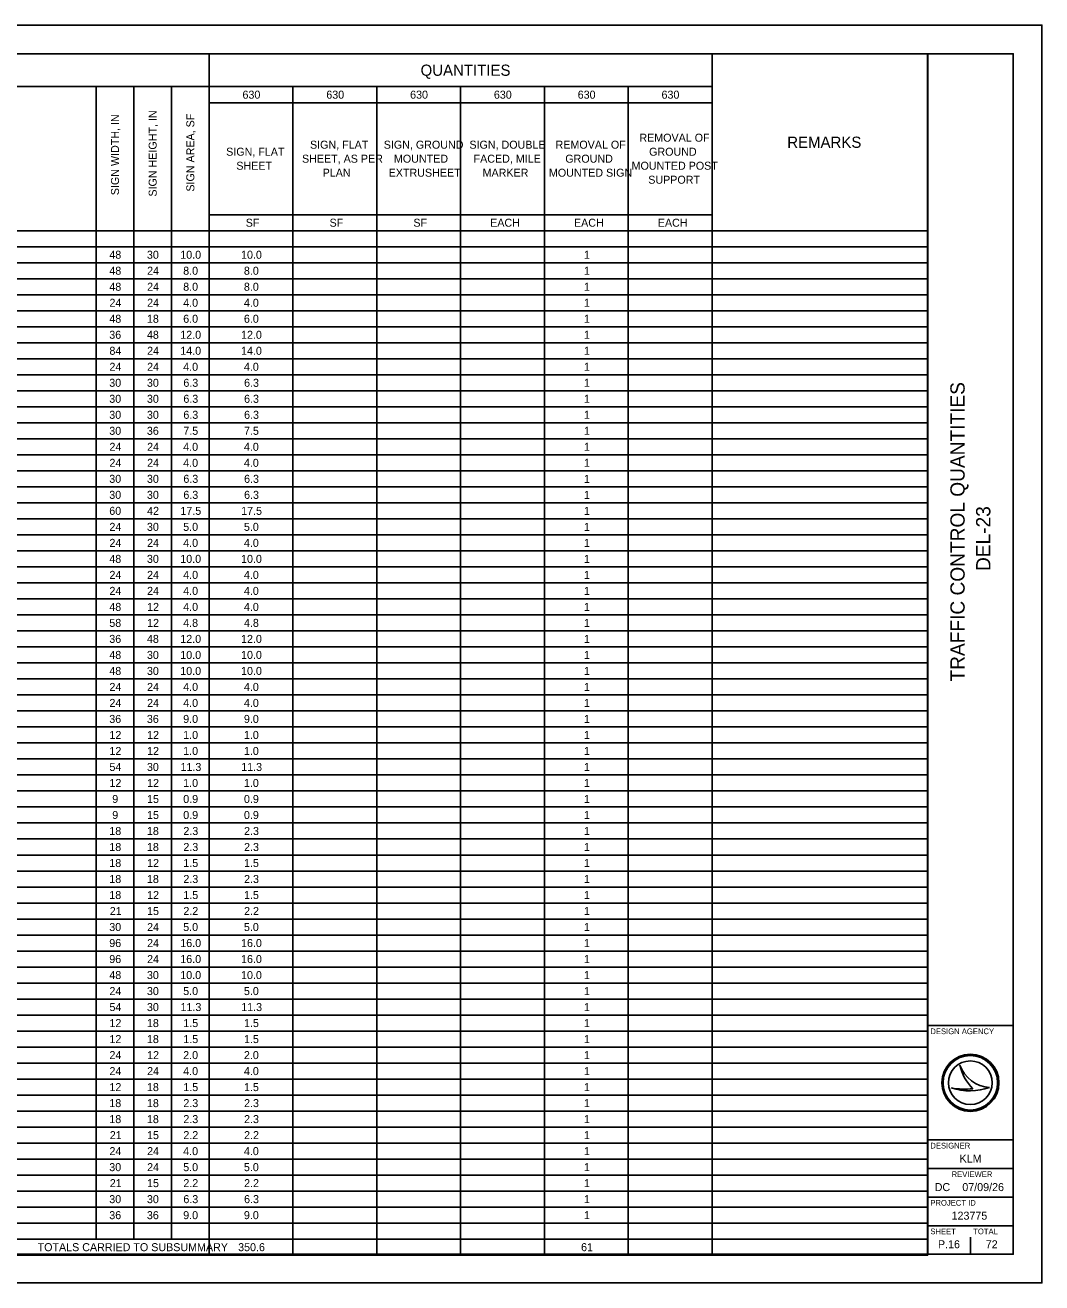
# Model space of a CAD drawing. Extents: x 0 to 34, y 0 to 22.
# Drawn here: x 16.22 to 34, y 0 to 22 of the extents above; entities that cross this region are included whole.
import ezdxf

# ---------------------------------------------------------------- set-up
doc = ezdxf.new("R2010")
doc.units = 0
for name, color, linetype in [('Default', 7, 'Continuous'), ('SH_Border', 7, 'Continuous'), ('SH_Cut_Line', 7, 'Continuous'), ('SH_Data', 7, 'Continuous')]:
    doc.layers.add(name, color=color, linetype=linetype)

msp = doc.modelspace()

# ---------------------------------------------------------------- linework, layer by layer
at = {"layer": 'SH_Border'}
for p, q in [((32, 0.5), (32, 21.5)), ((32, 4.5), (33.5, 4.5)), ((32, 2.5), (33.5, 2.5)), ((32, 2), (33.5, 2)), ((32, 1.5), (33.5, 1.5)), ((32, 1), (33.5, 1))]:
    msp.add_line(p, q, dxfattribs=at)
msp.add_lwpolyline([(1.5, 21.5), (33.5, 21.5), (33.5, 0.5), (1.5, 0.5)], close=True, dxfattribs=at)
at = {"layer": 'SH_Cut_Line'}
msp.add_lwpolyline([(0, 0), (34, 0), (34, 22), (0, 22)], close=True, dxfattribs=at)
at = {"layer": 'SH_Data'}
for p, q in [((1.5, 21.5), (32.004, 21.5)), ((19.436, 21.5), (19.436, 0.484)), ((28.232, 21.5), (28.232, 0.484)), ((32.004, 21.5), (32.004, 0.484)), ((1.5, 20.924), (28.232, 20.924)), ((17.46, 20.924), (17.46, 0.764)), ((18.119, 20.924), (18.119, 0.764)), ((18.778, 20.924), (18.778, 0.764)), ((20.902, 20.924), (20.902, 0.484)), ((22.368, 20.924), (22.368, 0.484)), ((23.834, 20.924), (23.834, 0.484)), ((25.3, 20.924), (25.3, 0.484)), ((26.766, 20.924), (26.766, 0.484)), ((19.436, 20.644), (28.232, 20.644)), ((19.436, 18.684), (28.232, 18.684)), ((1.5, 18.404), (32.004, 18.404)), ((1.5, 18.124), (32.004, 18.124)), ((1.5, 17.844), (32.004, 17.844)), ((1.5, 17.564), (32.004, 17.564)), ((1.5, 17.284), (32.004, 17.284)), ((1.5, 17.004), (32.004, 17.004)), ((1.5, 16.724), (32.004, 16.724)), ((1.5, 16.444), (32.004, 16.444)), ((1.5, 16.164), (32.004, 16.164)), ((1.5, 15.884), (32.004, 15.884)), ((1.5, 15.604), (32.004, 15.604)), ((1.5, 15.324), (32.004, 15.324)), ((1.5, 15.044), (32.004, 15.044)), ((1.5, 14.764), (32.004, 14.764)), ((1.5, 14.484), (32.004, 14.484)), ((1.5, 14.204), (32.004, 14.204)), ((1.5, 13.924), (32.004, 13.924)), ((1.5, 13.644), (32.004, 13.644)), ((1.5, 13.364), (32.004, 13.364)), ((1.5, 13.084), (32.004, 13.084)), ((1.5, 12.804), (32.004, 12.804)), ((1.5, 12.524), (32.004, 12.524)), ((1.5, 12.244), (32.004, 12.244)), ((1.5, 11.964), (32.004, 11.964)), ((1.5, 11.684), (32.004, 11.684)), ((1.5, 11.404), (32.004, 11.404)), ((1.5, 11.124), (32.004, 11.124)), ((1.5, 10.844), (32.004, 10.844)), ((1.5, 10.564), (32.004, 10.564)), ((1.5, 10.284), (32.004, 10.284)), ((1.5, 10.004), (32.004, 10.004)), ((1.5, 9.724), (32.004, 9.724)), ((1.5, 9.444), (32.004, 9.444)), ((1.5, 9.164), (32.004, 9.164)), ((1.5, 8.884), (32.004, 8.884)), ((1.5, 8.604), (32.004, 8.604)), ((1.5, 8.324), (32.004, 8.324)), ((1.5, 8.044), (32.004, 8.044)), ((1.5, 7.764), (32.004, 7.764)), ((1.5, 7.484), (32.004, 7.484)), ((1.5, 7.204), (32.004, 7.204)), ((1.5, 6.924), (32.004, 6.924)), ((1.5, 6.644), (32.004, 6.644)), ((1.5, 6.364), (32.004, 6.364)), ((1.5, 6.084), (32.004, 6.084)), ((1.5, 5.804), (32.004, 5.804)), ((1.5, 5.524), (32.004, 5.524)), ((1.5, 5.244), (32.004, 5.244)), ((1.5, 4.964), (32.004, 4.964)), ((1.5, 4.684), (32.004, 4.684)), ((1.5, 4.404), (32.004, 4.404)), ((1.5, 4.124), (32.004, 4.124)), ((1.5, 3.844), (32.004, 3.844)), ((32.567, 3.81), (32.567, 3.81)), ((1.5, 3.564), (32.004, 3.564)), ((32.417, 3.41), (32.417, 3.41)), ((32.75, 3.5), (32.75, 3.5)), ((33.087, 3.419), (33.087, 3.419)), ((1.5, 3.284), (32.004, 3.284)), ((1.5, 3.004), (32.004, 3.004)), ((1.5, 2.724), (32.004, 2.724)), ((1.5, 2.444), (32.004, 2.444)), ((1.5, 2.164), (32.004, 2.164)), ((1.5, 1.884), (32.004, 1.884)), ((1.5, 1.604), (32.004, 1.604)), ((1.5, 1.324), (32.004, 1.324)), ((1.5, 1.044), (32.004, 1.044)), ((1.5, 0.764), (32.004, 0.764)), ((32.375, 0.675), (32.375, 0.675)), ((32.75, 0.5), (32.75, 0.8)), ((1.5, 0.484), (32.004, 0.484))]:
    msp.add_line(p, q, dxfattribs=at)
for radius in [0.5, 0.477, 0.477, 0.382]:
    msp.add_circle((32.75, 3.5), radius, dxfattribs=at)
for centre, radius, start, end in [((33.116, 3.998), 0.58, 198.9257, 198.9319), ((33.347, 3.97), 0.796, 191.6379, 191.6421), ((33.116, 3.998), 0.58, 198.9319, 267.1657), ((33.347, 3.97), 0.796, 191.6421, 226.0947), ((32.739, 4.37), 1.013, 251.4576, 290.0832), ((32.648, 4.654), 1.266, 259.4964, 259.4995), ((32.739, 4.37), 1.013, 251.4527, 251.4576), ((32.648, 4.654), 1.266, 259.4995, 276.6672)]:
    msp.add_arc(centre, radius, start, end, dxfattribs=at)

# ---------------------------------------------------------------- texts
at = {"layer": 'Default'}
for s, height, p in [('QUANTITIES', 0.196, (23.134, 21.114)), ('630', 0.14, (20.019, 20.714)), ('630', 0.14, (21.485, 20.714)), ('630', 0.14, (22.951, 20.714)), ('630', 0.14, (24.416, 20.714)), ('630', 0.14, (25.882, 20.714)), ('630', 0.14, (27.348, 20.714)), ('REMOVAL OF ', 0.14, (26.961, 19.961)), ('REMARKS', 0.196, (29.547, 19.854)), ('SIGN, FLAT ', 0.14, (19.734, 19.716)), ('SIGN, FLAT ', 0.14, (21.2, 19.839)), ('SIGN, GROUND ', 0.14, (22.49, 19.839)), ('SIGN, DOUBLE ', 0.14, (23.988, 19.839)), ('REMOVAL OF ', 0.14, (25.495, 19.839)), ('GROUND ', 0.14, (27.131, 19.716)), ('SHEET', 0.14, (19.911, 19.471)), ('SHEET, AS PER ', 0.14, (21.06, 19.594)), ('MOUNTED ', 0.14, (22.668, 19.594)), ('FACED, MILE ', 0.14, (24.061, 19.594)), ('GROUND ', 0.14, (25.665, 19.594)), ('MOUNTED POST ', 0.14, (26.825, 19.471)), ('PLAN', 0.14, (21.421, 19.349)), ('EXTRUSHEET', 0.14, (22.576, 19.349)), ('MARKER', 0.14, (24.219, 19.349)), ('MOUNTED SIGN', 0.14, (25.379, 19.349)), ('SUPPORT', 0.14, (27.116, 19.226)), ('SF', 0.14, (20.076, 18.474)), ('SF', 0.14, (21.542, 18.474)), ('SF', 0.14, (23.008, 18.474)), ('EACH', 0.14, (24.351, 18.474)), ('EACH', 0.14, (25.817, 18.474)), ('EACH', 0.14, (27.283, 18.474)), ('48', 0.14, (17.69, 17.914)), ('30', 0.14, (18.348, 17.914)), ('10.0', 0.14, (18.931, 17.914)), ('10.0', 0.14, (19.994, 17.914)), ('1', 0.14, (25.992, 17.914)), ('48', 0.14, (17.69, 17.634)), ('24', 0.14, (18.351, 17.634)), ('8.0', 0.14, (18.982, 17.634)), ('8.0', 0.14, (20.044, 17.634)), ('1', 0.14, (25.992, 17.634)), ('48', 0.14, (17.69, 17.354)), ('24', 0.14, (18.351, 17.354)), ('8.0', 0.14, (18.982, 17.354)), ('8.0', 0.14, (20.044, 17.354)), ('1', 0.14, (25.992, 17.354)), ('24', 0.14, (17.692, 17.074)), ('24', 0.14, (18.351, 17.074)), ('4.0', 0.14, (18.982, 17.074)), ('4.0', 0.14, (20.044, 17.074)), ('1', 0.14, (25.992, 17.074)), ('48', 0.14, (17.69, 16.794)), ('18', 0.14, (18.348, 16.794)), ('6.0', 0.14, (18.982, 16.794)), ('6.0', 0.14, (20.044, 16.794)), ('1', 0.14, (25.992, 16.794)), ('36', 0.14, (17.689, 16.514)), ('48', 0.14, (18.348, 16.514)), ('12.0', 0.14, (18.931, 16.514)), ('12.0', 0.14, (19.994, 16.514)), ('1', 0.14, (25.992, 16.514)), ('84', 0.14, (17.692, 16.234)), ('24', 0.14, (18.351, 16.234)), ('14.0', 0.14, (18.931, 16.234)), ('14.0', 0.14, (19.994, 16.234)), ('1', 0.14, (25.992, 16.234)), ('24', 0.14, (17.692, 15.954)), ('24', 0.14, (18.351, 15.954)), ('4.0', 0.14, (18.982, 15.954)), ('4.0', 0.14, (20.044, 15.954)), ('1', 0.14, (25.992, 15.954)), ('30', 0.14, (17.689, 15.674)), ('30', 0.14, (18.348, 15.674)), ('6.3', 0.14, (18.985, 15.674)), ('6.3', 0.14, (20.047, 15.674)), ('1', 0.14, (25.992, 15.674)), ('30', 0.14, (17.689, 15.394)), ('30', 0.14, (18.348, 15.394)), ('6.3', 0.14, (18.985, 15.394)), ('6.3', 0.14, (20.047, 15.394)), ('1', 0.14, (25.992, 15.394)), ('30', 0.14, (17.689, 15.114)), ('30', 0.14, (18.348, 15.114)), ('6.3', 0.14, (18.985, 15.114)), ('6.3', 0.14, (20.047, 15.114)), ('1', 0.14, (25.992, 15.114)), ('30', 0.14, (17.689, 14.834)), ('36', 0.14, (18.347, 14.834)), ('7.5', 0.14, (18.984, 14.834)), ('7.5', 0.14, (20.046, 14.834)), ('1', 0.14, (25.992, 14.834)), ('24', 0.14, (17.692, 14.554)), ('24', 0.14, (18.351, 14.554)), ('4.0', 0.14, (18.982, 14.554)), ('4.0', 0.14, (20.044, 14.554)), ('1', 0.14, (25.992, 14.554)), ('24', 0.14, (17.692, 14.274)), ('24', 0.14, (18.351, 14.274)), ('4.0', 0.14, (18.982, 14.274)), ('4.0', 0.14, (20.044, 14.274)), ('1', 0.14, (25.992, 14.274)), ('30', 0.14, (17.689, 13.994)), ('30', 0.14, (18.348, 13.994)), ('6.3', 0.14, (18.985, 13.994)), ('6.3', 0.14, (20.047, 13.994)), ('1', 0.14, (25.992, 13.994)), ('30', 0.14, (17.689, 13.714)), ('30', 0.14, (18.348, 13.714)), ('6.3', 0.14, (18.985, 13.714)), ('6.3', 0.14, (20.047, 13.714)), ('1', 0.14, (25.992, 13.714)), ('60', 0.14, (17.689, 13.434)), ('42', 0.14, (18.351, 13.434)), ('17.5', 0.14, (18.933, 13.434)), ('17.5', 0.14, (19.996, 13.434)), ('1', 0.14, (25.992, 13.434)), ('24', 0.14, (17.692, 13.154)), ('30', 0.14, (18.348, 13.154)), ('5.0', 0.14, (18.982, 13.154)), ('5.0', 0.14, (20.044, 13.154)), ('1', 0.14, (25.992, 13.154)), ('24', 0.14, (17.692, 12.874)), ('24', 0.14, (18.351, 12.874)), ('4.0', 0.14, (18.982, 12.874)), ('4.0', 0.14, (20.044, 12.874)), ('1', 0.14, (25.992, 12.874)), ('48', 0.14, (17.69, 12.594)), ('30', 0.14, (18.348, 12.594)), ('10.0', 0.14, (18.931, 12.594)), ('10.0', 0.14, (19.994, 12.594)), ('1', 0.14, (25.992, 12.594)), ('24', 0.14, (17.692, 12.314)), ('24', 0.14, (18.351, 12.314)), ('4.0', 0.14, (18.982, 12.314)), ('4.0', 0.14, (20.044, 12.314)), ('1', 0.14, (25.992, 12.314)), ('24', 0.14, (17.692, 12.034)), ('24', 0.14, (18.351, 12.034)), ('4.0', 0.14, (18.982, 12.034)), ('4.0', 0.14, (20.044, 12.034)), ('1', 0.14, (25.992, 12.034)), ('48', 0.14, (17.69, 11.754)), ('12', 0.14, (18.351, 11.754)), ('4.0', 0.14, (18.982, 11.754)), ('4.0', 0.14, (20.044, 11.754)), ('1', 0.14, (25.992, 11.754)), ('58', 0.14, (17.69, 11.474)), ('12', 0.14, (18.351, 11.474)), ('4.8', 0.14, (18.982, 11.474)), ('4.8', 0.14, (20.045, 11.474)), ('1', 0.14, (25.992, 11.474)), ('36', 0.14, (17.689, 11.194)), ('48', 0.14, (18.348, 11.194)), ('12.0', 0.14, (18.931, 11.194)), ('12.0', 0.14, (19.994, 11.194)), ('1', 0.14, (25.992, 11.194)), ('48', 0.14, (17.69, 10.914)), ('30', 0.14, (18.348, 10.914)), ('10.0', 0.14, (18.931, 10.914)), ('10.0', 0.14, (19.994, 10.914)), ('1', 0.14, (25.992, 10.914)), ('48', 0.14, (17.69, 10.634)), ('30', 0.14, (18.348, 10.634)), ('10.0', 0.14, (18.931, 10.634)), ('10.0', 0.14, (19.994, 10.634)), ('1', 0.14, (25.992, 10.634)), ('24', 0.14, (17.692, 10.354)), ('24', 0.14, (18.351, 10.354)), ('4.0', 0.14, (18.982, 10.354)), ('4.0', 0.14, (20.044, 10.354)), ('1', 0.14, (25.992, 10.354)), ('24', 0.14, (17.692, 10.074)), ('24', 0.14, (18.351, 10.074)), ('4.0', 0.14, (18.982, 10.074)), ('4.0', 0.14, (20.044, 10.074)), ('1', 0.14, (25.992, 10.074)), ('36', 0.14, (17.689, 9.794)), ('36', 0.14, (18.347, 9.794)), ('9.0', 0.14, (18.982, 9.794)), ('9.0', 0.14, (20.044, 9.794)), ('1', 0.14, (25.992, 9.794)), ('12', 0.14, (17.692, 9.514)), ('12', 0.14, (18.351, 9.514)), ('1.0', 0.14, (18.982, 9.514)), ('1.0', 0.14, (20.044, 9.514)), ('1', 0.14, (25.992, 9.514)), ('12', 0.14, (17.692, 9.234)), ('12', 0.14, (18.351, 9.234)), ('1.0', 0.14, (18.982, 9.234)), ('1.0', 0.14, (20.044, 9.234)), ('1', 0.14, (25.992, 9.234)), ('54', 0.14, (17.692, 8.954)), ('30', 0.14, (18.348, 8.954)), ('11.3', 0.14, (18.935, 8.954)), ('11.3', 0.14, (19.997, 8.954)), ('1', 0.14, (25.992, 8.954)), ('12', 0.14, (17.692, 8.674)), ('12', 0.14, (18.351, 8.674)), ('1.0', 0.14, (18.982, 8.674)), ('1.0', 0.14, (20.044, 8.674)), ('1', 0.14, (25.992, 8.674)), ('9', 0.14, (17.741, 8.394)), ('15', 0.14, (18.35, 8.394)), ('0.9', 0.14, (18.983, 8.394)), ('0.9', 0.14, (20.045, 8.394)), ('1', 0.14, (25.992, 8.394)), ('9', 0.14, (17.741, 8.114)), ('15', 0.14, (18.35, 8.114)), ('0.9', 0.14, (18.983, 8.114)), ('0.9', 0.14, (20.045, 8.114)), ('1', 0.14, (25.992, 8.114)), ('18', 0.14, (17.69, 7.834)), ('18', 0.14, (18.348, 7.834)), ('2.3', 0.14, (18.985, 7.834)), ('2.3', 0.14, (20.047, 7.834)), ('1', 0.14, (25.992, 7.834)), ('18', 0.14, (17.69, 7.554)), ('18', 0.14, (18.348, 7.554)), ('2.3', 0.14, (18.985, 7.554)), ('2.3', 0.14, (20.047, 7.554)), ('1', 0.14, (25.992, 7.554)), ('18', 0.14, (17.69, 7.274)), ('12', 0.14, (18.351, 7.274)), ('1.5', 0.14, (18.984, 7.274)), ('1.5', 0.14, (20.046, 7.274)), ('1', 0.14, (25.992, 7.274)), ('18', 0.14, (17.69, 6.994)), ('18', 0.14, (18.348, 6.994)), ('2.3', 0.14, (18.985, 6.994)), ('2.3', 0.14, (20.047, 6.994)), ('1', 0.14, (25.992, 6.994)), ('18', 0.14, (17.69, 6.714)), ('12', 0.14, (18.351, 6.714)), ('1.5', 0.14, (18.984, 6.714)), ('1.5', 0.14, (20.046, 6.714)), ('1', 0.14, (25.992, 6.714)), ('21', 0.14, (17.698, 6.434)), ('15', 0.14, (18.35, 6.434)), ('2.2', 0.14, (18.985, 6.434)), ('2.2', 0.14, (20.047, 6.434)), ('1', 0.14, (25.992, 6.434)), ('30', 0.14, (17.689, 6.154)), ('24', 0.14, (18.351, 6.154)), ('5.0', 0.14, (18.982, 6.154)), ('5.0', 0.14, (20.044, 6.154)), ('1', 0.14, (25.992, 6.154)), ('96', 0.14, (17.689, 5.874)), ('24', 0.14, (18.351, 5.874)), ('16.0', 0.14, (18.931, 5.874)), ('16.0', 0.14, (19.994, 5.874)), ('1', 0.14, (25.992, 5.874)), ('96', 0.14, (17.689, 5.594)), ('24', 0.14, (18.351, 5.594)), ('16.0', 0.14, (18.931, 5.594)), ('16.0', 0.14, (19.994, 5.594)), ('1', 0.14, (25.992, 5.594)), ('48', 0.14, (17.69, 5.314)), ('30', 0.14, (18.348, 5.314)), ('10.0', 0.14, (18.931, 5.314)), ('10.0', 0.14, (19.994, 5.314)), ('1', 0.14, (25.992, 5.314)), ('24', 0.14, (17.692, 5.034)), ('30', 0.14, (18.348, 5.034)), ('5.0', 0.14, (18.982, 5.034)), ('5.0', 0.14, (20.044, 5.034)), ('1', 0.14, (25.992, 5.034)), ('54', 0.14, (17.692, 4.754)), ('30', 0.14, (18.348, 4.754)), ('11.3', 0.14, (18.935, 4.754)), ('11.3', 0.14, (19.997, 4.754)), ('1', 0.14, (25.992, 4.754)), ('12', 0.14, (17.692, 4.474)), ('18', 0.14, (18.348, 4.474)), ('1.5', 0.14, (18.984, 4.474)), ('1.5', 0.14, (20.046, 4.474)), ('1', 0.14, (25.992, 4.474)), ('12', 0.14, (17.692, 4.194)), ('18', 0.14, (18.348, 4.194)), ('1.5', 0.14, (18.984, 4.194)), ('1.5', 0.14, (20.046, 4.194)), ('1', 0.14, (25.992, 4.194)), ('24', 0.14, (17.692, 3.914)), ('12', 0.14, (18.351, 3.914)), ('2.0', 0.14, (18.982, 3.914)), ('2.0', 0.14, (20.044, 3.914)), ('1', 0.14, (25.992, 3.914)), ('24', 0.14, (17.692, 3.634)), ('24', 0.14, (18.351, 3.634)), ('4.0', 0.14, (18.982, 3.634)), ('4.0', 0.14, (20.044, 3.634)), ('1', 0.14, (25.992, 3.634)), ('12', 0.14, (17.692, 3.354)), ('18', 0.14, (18.348, 3.354)), ('1.5', 0.14, (18.984, 3.354)), ('1.5', 0.14, (20.046, 3.354)), ('1', 0.14, (25.992, 3.354)), ('18', 0.14, (17.69, 3.074)), ('18', 0.14, (18.348, 3.074)), ('2.3', 0.14, (18.985, 3.074)), ('2.3', 0.14, (20.047, 3.074)), ('1', 0.14, (25.992, 3.074)), ('18', 0.14, (17.69, 2.794)), ('18', 0.14, (18.348, 2.794)), ('2.3', 0.14, (18.985, 2.794)), ('2.3', 0.14, (20.047, 2.794)), ('1', 0.14, (25.992, 2.794)), ('21', 0.14, (17.698, 2.514)), ('15', 0.14, (18.35, 2.514)), ('2.2', 0.14, (18.985, 2.514)), ('2.2', 0.14, (20.047, 2.514)), ('1', 0.14, (25.992, 2.514)), ('24', 0.14, (17.692, 2.234)), ('24', 0.14, (18.351, 2.234)), ('4.0', 0.14, (18.982, 2.234)), ('4.0', 0.14, (20.044, 2.234)), ('1', 0.14, (25.992, 2.234)), ('30', 0.14, (17.689, 1.954)), ('24', 0.14, (18.351, 1.954)), ('5.0', 0.14, (18.982, 1.954)), ('5.0', 0.14, (20.044, 1.954)), ('1', 0.14, (25.992, 1.954)), ('21', 0.14, (17.698, 1.674)), ('15', 0.14, (18.35, 1.674)), ('2.2', 0.14, (18.985, 1.674)), ('2.2', 0.14, (20.047, 1.674)), ('1', 0.14, (25.992, 1.674)), ('30', 0.14, (17.689, 1.394)), ('30', 0.14, (18.348, 1.394)), ('6.3', 0.14, (18.985, 1.394)), ('6.3', 0.14, (20.047, 1.394)), ('1', 0.14, (25.992, 1.394)), ('36', 0.14, (17.689, 1.114)), ('36', 0.14, (18.347, 1.114)), ('9.0', 0.14, (18.982, 1.114)), ('9.0', 0.14, (20.044, 1.114)), ('1', 0.14, (25.992, 1.114)), ('TOTALS CARRIED TO SUBSUMMARY', 0.14, (16.436, 0.554)), ('350.6', 0.14, (19.943, 0.554)), ('61', 0.14, (25.941, 0.554))]:
    msp.add_text(s, height=height, dxfattribs=at).set_placement(p)
for s, p in [('SIGN HEIGHT, IN', (18.518, 19.001)), ('SIGN WIDTH, IN', (17.859, 19.026)), ('SIGN AREA, SF', (19.177, 19.088))]:
    msp.add_text(s, height=0.14, rotation=90, dxfattribs=at).set_placement(p)
at = {"layer": 'SH_Data'}
for s, p in [('TRAFFIC CONTROL QUANTITIES', (32.65, 10.519)), ('DEL-23', (33.1, 12.452))]:
    msp.add_text(s, height=0.25, rotation=90, dxfattribs=at).set_placement(p)
for s, height, p in [('DESIGN AGENCY', 0.1, (32.05, 4.35)), ('DESIGNER', 0.1, (32.05, 2.35)), ('KLM', 0.14, (32.561, 2.105)), ('REVIEWER', 0.1, (32.422, 1.85)), ('DC', 0.14, (32.126, 1.605)), ('07/09/26', 0.14, (32.609, 1.605)), ('PROJECT ID', 0.1, (32.05, 1.35)), ('123775', 0.14, (32.421, 1.105)), ('SHEET', 0.1, (32.05, 0.85)), ('TOTAL', 0.1, (32.8, 0.85)), ('P.16', 0.14, (32.183, 0.605)), ('72', 0.14, (33.019, 0.605))]:
    msp.add_text(s, height=height, dxfattribs=at).set_placement(p)

doc.saveas('drawing.dxf')
